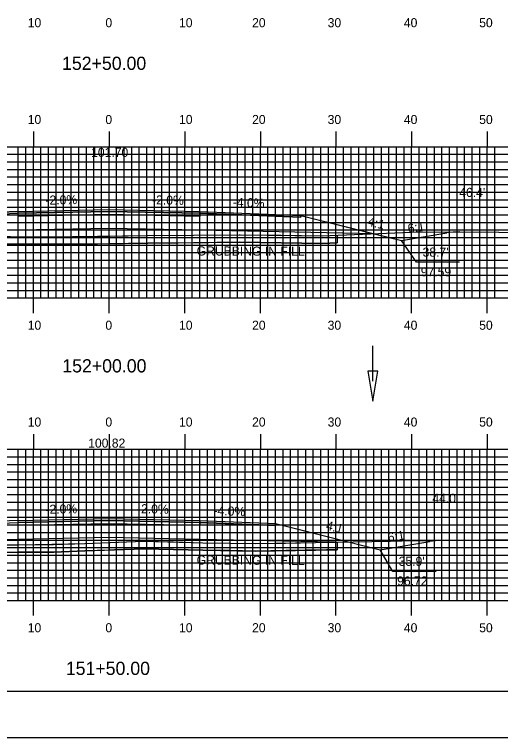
# Model space of a CAD drawing. Extents: x 1778712 to 1779055, y 442591 to 442811.
# Drawn here: x 1778865.3 to 1778929.6, y 442590.5 to 442686.2 of the extents above; entities that cross this region are included whole.
import ezdxf

# ---------------------------------------------------------------- set-up
doc = ezdxf.new("R2010")
doc.units = 0
for name, color, linetype in [('ANNOTATION', 7, 'Continuous'), ('BORDER', 7, 'Continuous'), ('D_Drainage_Ditch_Line', 7, 'Continuous'), ('D_Roadway_Centerline', 7, 'Continuous'), ('D_Roadway_Centerline_Text', 7, 'Continuous'), ('D_Roadway_Edge_Shoulder', 7, 'Continuous'), ('D_Roadway_Edge_TW', 7, 'Continuous'), ('D_Roadway_Pavement', 7, 'Continuous'), ('D_Roadway_SlopeLines', 7, 'Continuous'), ('D_Roadway_SubGrade', 7, 'Continuous'), ('D_Text_Standard', 7, 'Continuous'), ('GRUBBING IN FILL', 7, 'Continuous'), ('H_V ANNOTATION', 7, 'Continuous'), ('MAJOR', 7, 'Continuous'), ('MINOR', 7, 'Continuous'), ('PLOT BOUNDARY', 7, 'Continuous'), ('S_Roadway_Centerline', 7, 'Continuous')]:
    doc.layers.add(name, color=color, linetype=linetype)

msp = doc.modelspace()

# ---------------------------------------------------------------- linework, layer by layer
at = {"layer": 'ANNOTATION'}
for points in [[(1778924.146, 442653.401), (1778918.454, 442653.401), (1778916.47, 442656.259)], [(1778921.039, 442612.52), (1778915.347, 442612.52), (1778913.67, 442615.384)]]:
    msp.add_lwpolyline(points, dxfattribs=at)
at = {"layer": 'BORDER'}
msp.add_lwpolyline([(1778728.216, 442596.665), (1779048.216, 442596.665), (1779048.216, 442806.665), (1778728.216, 442806.665)], close=True, dxfattribs=at)
at = {"layer": 'D_Drainage_Ditch_Line'}
msp.add_line((1778912.679, 442637.661), (1778912.678, 442642.36), dxfattribs=at)
msp.add_lwpolyline([(1778913.335, 442638.974), (1778912.022, 442638.974), (1778912.679, 442635.037)], close=True, dxfattribs=at)
at = {"layer": 'D_Roadway_Centerline'}
msp.add_lwpolyline([(1778842.631, 442656.331), (1778842.722, 442656.331), (1778842.883, 442656.331), (1778843.136, 442656.319), (1778843.376, 442656.296), (1778843.389, 442656.295), (1778843.41, 442656.292), (1778843.642, 442656.259), (1778846.32, 442656.929), (1778847.642, 442657.259), (1778857.816, 442659.802), (1778859.485, 442659.869), (1778865.816, 442660.122), (1778877.816, 442660.362), (1778881.804, 442660.282), (1778889.816, 442660.122), (1778903.149, 442659.589), (1778912.858, 442657.162), (1778916.47, 442656.259)], dxfattribs=at)
at = {"layer": 'D_Roadway_Edge_Shoulder'}
for points in [[(1778865.816, 442660.122), (1778857.816, 442659.802), (1778857.816, 442659.552), (1778865.816, 442659.872)], [(1778889.816, 442660.122), (1778903.149, 442659.589), (1778903.149, 442659.339), (1778889.816, 442659.872)], [(1778865.816, 442619.247), (1778857.816, 442618.927), (1778857.816, 442618.677), (1778865.816, 442618.997)], [(1778889.816, 442619.247), (1778899.816, 442618.847), (1778899.816, 442618.597), (1778889.816, 442618.997)]]:
    msp.add_lwpolyline(points, close=True, dxfattribs=at)
at = {"layer": 'D_Roadway_Edge_TW'}
for points in [[(1778865.816, 442659.872), (1778865.816, 442660.122), (1778877.816, 442660.362), (1778889.816, 442660.122), (1778889.816, 442659.872), (1778877.816, 442660.112)], [(1778865.816, 442618.997), (1778865.816, 442619.247), (1778877.816, 442619.487), (1778889.816, 442619.247), (1778889.816, 442618.997), (1778877.816, 442619.237)]]:
    msp.add_lwpolyline(points, close=True, dxfattribs=at)
at = {"layer": 'D_Roadway_Pavement'}
for points in [[(1778865.816, 442659.456), (1778865.816, 442659.872), (1778877.816, 442660.112), (1778889.816, 442659.872), (1778889.816, 442659.456), (1778877.816, 442659.696)], [(1778865.816, 442618.581), (1778865.816, 442618.997), (1778877.816, 442619.237), (1778889.816, 442618.997), (1778889.816, 442618.581), (1778877.816, 442618.821)]]:
    msp.add_lwpolyline(points, close=True, dxfattribs=at)
at = {"layer": 'D_Roadway_SlopeLines'}
for points in [[(1778903.149, 442659.589), (1778916.47, 442656.259)], [(1778916.47, 442656.259), (1778922.458, 442657.258)], [(1778899.816, 442618.847), (1778913.67, 442615.384)], [(1778913.67, 442615.384), (1778920.204, 442616.473)]]:
    msp.add_lwpolyline(points, dxfattribs=at)
for centre, start, end in [((1778924.103, 442647.394), 89.59856, 99.46701), ((1778921.848, 442606.609), 90.80497, 99.46232)]:
    msp.add_arc(centre, 10, start, end, dxfattribs=at)
at = {"layer": 'D_Roadway_SubGrade'}
for points in [[(1778865.816, 442657.622), (1778847.642, 442657.259), (1778857.816, 442659.802), (1778857.816, 442659.552), (1778865.816, 442659.872), (1778877.816, 442660.112), (1778889.816, 442659.872), (1778903.149, 442659.339), (1778903.149, 442659.589), (1778912.858, 442657.162), (1778889.816, 442657.622), (1778877.816, 442657.862)], [(1778865.816, 442616.747), (1778847.642, 442616.384), (1778857.816, 442618.927), (1778857.816, 442618.677), (1778865.816, 442618.997), (1778877.816, 442619.237), (1778889.816, 442618.997), (1778899.816, 442618.597), (1778899.816, 442618.847), (1778909.815, 442616.348), (1778889.816, 442616.747), (1778877.816, 442616.987)]]:
    msp.add_lwpolyline(points, close=True, dxfattribs=at)
at = {"layer": 'GRUBBING IN FILL'}
for p, q in [((1778907.99, 442656.971), (1778907.99, 442655.97)), ((1778907.99, 442656.971), (1778907.99, 442655.97)), ((1778907.99, 442616.371), (1778907.99, 442615.371)), ((1778907.99, 442616.371), (1778907.99, 442615.371))]:
    msp.add_line(p, q, dxfattribs=at)
for points in [[(1778847.642, 442656.456), (1778848.306, 442656.475), (1778850.185, 442656.529), (1778854.875, 442656.682), (1778859.566, 442656.834), (1778864.784, 442656.8), (1778870.002, 442656.765), (1778872.983, 442656.777), (1778877.816, 442656.845), (1778877.816, 442655.845), (1778872.992, 442655.777), (1778870.001, 442655.765), (1778864.79, 442655.8), (1778859.579, 442655.834), (1778854.897, 442655.682), (1778847.642, 442655.456)], [(1778847.642, 442656.456), (1778848.306, 442656.475), (1778850.185, 442656.529), (1778854.875, 442656.682), (1778859.566, 442656.834), (1778864.784, 442656.8), (1778870.002, 442656.765), (1778872.983, 442656.777), (1778877.816, 442656.845), (1778877.816, 442655.845), (1778872.992, 442655.777), (1778870.001, 442655.765), (1778864.79, 442655.8), (1778859.579, 442655.834), (1778854.897, 442655.682), (1778847.642, 442655.456)], [(1778877.816, 442656.845), (1778882.913, 442656.917), (1778888.971, 442656.977), (1778895.158, 442657.035), (1778900.582, 442656.96), (1778906.006, 442656.886), (1778907.99, 442656.971), (1778907.99, 442655.97), (1778907.005, 442655.928), (1778906.02, 442655.886), (1778900.583, 442655.96), (1778895.114, 442656.035), (1778888.976, 442655.977), (1778882.925, 442655.917), (1778877.816, 442655.845)], [(1778877.816, 442656.845), (1778882.913, 442656.917), (1778888.971, 442656.977), (1778895.158, 442657.035), (1778900.582, 442656.96), (1778906.006, 442656.886), (1778907.99, 442656.971), (1778907.99, 442655.97), (1778907.005, 442655.928), (1778906.02, 442655.886), (1778900.583, 442655.96), (1778895.114, 442656.035), (1778888.976, 442655.977), (1778882.925, 442655.917), (1778877.816, 442655.845)], [(1778847.642, 442614.901), (1778847.642, 442615.902), (1778851.685, 442616.011), (1778854.763, 442616.015), (1778861.781, 442616.033), (1778868.104, 442616.05), (1778874.6, 442616.221), (1778877.816, 442616.334), (1778877.816, 442615.333), (1778874.638, 442615.222), (1778870.508, 442615.053), (1778865.724, 442615.048), (1778857.843, 442615.018), (1778851.699, 442615.011)], [(1778847.642, 442614.901), (1778847.642, 442615.902), (1778851.685, 442616.011), (1778854.763, 442616.015), (1778861.781, 442616.033), (1778868.104, 442616.05), (1778874.6, 442616.221), (1778877.816, 442616.334), (1778877.816, 442615.333), (1778874.638, 442615.222), (1778870.508, 442615.053), (1778865.724, 442615.048), (1778857.843, 442615.018), (1778851.699, 442615.011)], [(1778877.816, 442616.334), (1778882.435, 442616.495), (1778886.333, 442616.403), (1778890.23, 442616.31), (1778893.722, 442616.26), (1778897.213, 442616.21), (1778901.162, 442616.266), (1778905.11, 442616.322), (1778907.99, 442616.371), (1778907.99, 442615.371), (1778906.558, 442615.347), (1778901.169, 442615.266), (1778897.213, 442615.21), (1778893.712, 442615.26), (1778890.211, 442615.311), (1778886.326, 442615.403), (1778882.441, 442615.495), (1778878.539, 442615.358), (1778877.816, 442615.333)], [(1778877.816, 442616.334), (1778882.435, 442616.495), (1778886.333, 442616.403), (1778890.23, 442616.31), (1778893.722, 442616.26), (1778897.213, 442616.21), (1778901.162, 442616.266), (1778905.11, 442616.322), (1778907.99, 442616.371), (1778907.99, 442615.371), (1778906.558, 442615.347), (1778901.169, 442615.266), (1778897.213, 442615.21), (1778893.712, 442615.26), (1778890.211, 442615.311), (1778886.326, 442615.403), (1778882.441, 442615.495), (1778878.539, 442615.358), (1778877.816, 442615.333)]]:
    msp.add_lwpolyline(points, close=True, dxfattribs=at)
for points in [[(1778847.642, 442655.456), (1778850.215, 442655.53), (1778859.579, 442655.834), (1778870.001, 442655.765), (1778872.992, 442655.777), (1778882.925, 442655.917), (1778895.028, 442656.037), (1778895.082, 442656.036), (1778895.146, 442656.035), (1778906.02, 442655.886), (1778907.99, 442655.97)], [(1778847.642, 442655.456), (1778850.215, 442655.53), (1778859.579, 442655.834), (1778870.001, 442655.765), (1778872.992, 442655.777), (1778882.925, 442655.917), (1778895.028, 442656.037), (1778895.082, 442656.036), (1778895.146, 442656.035), (1778906.02, 442655.886), (1778907.99, 442655.97)], [(1778847.642, 442614.901), (1778851.699, 442615.011), (1778857.843, 442615.018), (1778865.724, 442615.048), (1778870.508, 442615.053), (1778874.638, 442615.222), (1778882.441, 442615.495), (1778890.211, 442615.311), (1778897.213, 442615.21), (1778905.126, 442615.323), (1778907.99, 442615.371)], [(1778847.642, 442614.901), (1778851.699, 442615.011), (1778857.843, 442615.018), (1778865.724, 442615.048), (1778870.508, 442615.053), (1778874.638, 442615.222), (1778882.441, 442615.495), (1778890.211, 442615.311), (1778897.213, 442615.21), (1778905.126, 442615.323), (1778907.99, 442615.371)]]:
    msp.add_lwpolyline(points, dxfattribs=at)
at = {"layer": 'MAJOR'}
for p, q in [((1778867.816, 442670.669), (1778867.816, 442668.665)), ((1778877.816, 442670.669), (1778877.816, 442668.665)), ((1778887.816, 442670.669), (1778887.816, 442668.665)), ((1778897.816, 442670.669), (1778897.816, 442668.665)), ((1778907.816, 442670.669), (1778907.816, 442668.665)), ((1778917.816, 442670.669), (1778917.816, 442668.665)), ((1778927.816, 442670.669), (1778927.816, 442668.665)), ((1778737.816, 442668.665), (1779017.816, 442668.665)), ((1778737.816, 442668.665), (1779017.816, 442668.665)), ((1778867.816, 442648.665), (1778867.816, 442668.665)), ((1778877.816, 442648.665), (1778877.816, 442668.665)), ((1778887.816, 442648.665), (1778887.816, 442668.665)), ((1778897.816, 442648.665), (1778897.816, 442668.665)), ((1778907.816, 442648.665), (1778907.816, 442668.665)), ((1778917.816, 442648.665), (1778917.816, 442668.665)), ((1778927.816, 442648.665), (1778927.816, 442668.665)), ((1778737.816, 442663.665), (1779017.816, 442663.665)), ((1778737.816, 442658.665), (1779017.816, 442658.665)), ((1778737.816, 442653.665), (1779017.816, 442653.665)), ((1778737.816, 442648.665), (1779017.816, 442648.665)), ((1778737.816, 442648.665), (1779017.816, 442648.665)), ((1778867.816, 442646.661), (1778867.816, 442648.665)), ((1778877.816, 442646.661), (1778877.816, 442648.665)), ((1778887.816, 442646.661), (1778887.816, 442648.665)), ((1778897.816, 442646.661), (1778897.816, 442648.665)), ((1778907.816, 442646.661), (1778907.816, 442648.665)), ((1778917.816, 442646.661), (1778917.816, 442648.665)), ((1778927.816, 442646.661), (1778927.816, 442648.665)), ((1778867.816, 442630.669), (1778867.816, 442628.665)), ((1778877.816, 442630.669), (1778877.816, 442628.665)), ((1778887.816, 442630.669), (1778887.816, 442628.665)), ((1778897.816, 442630.669), (1778897.816, 442628.665)), ((1778907.816, 442630.669), (1778907.816, 442628.665)), ((1778917.816, 442630.669), (1778917.816, 442628.665)), ((1778927.816, 442630.669), (1778927.816, 442628.665)), ((1778737.816, 442628.665), (1779017.816, 442628.665)), ((1778737.816, 442628.665), (1779017.816, 442628.665)), ((1778867.816, 442608.665), (1778867.816, 442628.665)), ((1778877.816, 442608.665), (1778877.816, 442628.665)), ((1778887.816, 442608.665), (1778887.816, 442628.665)), ((1778897.816, 442608.665), (1778897.816, 442628.665)), ((1778907.816, 442608.665), (1778907.816, 442628.665)), ((1778917.816, 442608.665), (1778917.816, 442628.665)), ((1778927.816, 442608.665), (1778927.816, 442628.665)), ((1778737.816, 442623.665), (1779017.816, 442623.665)), ((1778737.816, 442618.665), (1779017.816, 442618.665)), ((1778737.816, 442613.665), (1779017.816, 442613.665)), ((1778737.816, 442608.665), (1779017.816, 442608.665)), ((1778737.816, 442608.665), (1779017.816, 442608.665)), ((1778867.816, 442606.661), (1778867.816, 442608.665)), ((1778877.816, 442606.661), (1778877.816, 442608.665)), ((1778887.816, 442606.661), (1778887.816, 442608.665)), ((1778897.816, 442606.661), (1778897.816, 442608.665)), ((1778907.816, 442606.661), (1778907.816, 442608.665)), ((1778917.816, 442606.661), (1778917.816, 442608.665)), ((1778927.816, 442606.661), (1778927.816, 442608.665))]:
    msp.add_line(p, q, dxfattribs=at)
at = {"layer": 'MINOR'}
for p, q in [((1778865.816, 442648.665), (1778865.816, 442668.665)), ((1778866.816, 442648.665), (1778866.816, 442668.665)), ((1778868.816, 442648.665), (1778868.816, 442668.665)), ((1778869.816, 442648.665), (1778869.816, 442668.665)), ((1778870.816, 442648.665), (1778870.816, 442668.665)), ((1778871.816, 442648.665), (1778871.816, 442668.665)), ((1778872.816, 442648.665), (1778872.816, 442668.665)), ((1778873.816, 442648.665), (1778873.816, 442668.665)), ((1778874.816, 442648.665), (1778874.816, 442668.665)), ((1778875.816, 442648.665), (1778875.816, 442668.665)), ((1778876.816, 442648.665), (1778876.816, 442668.665)), ((1778878.816, 442648.665), (1778878.816, 442668.665)), ((1778879.816, 442648.665), (1778879.816, 442668.665)), ((1778880.816, 442648.665), (1778880.816, 442668.665)), ((1778881.816, 442648.665), (1778881.816, 442668.665)), ((1778882.816, 442648.665), (1778882.816, 442668.665)), ((1778883.816, 442648.665), (1778883.816, 442668.665)), ((1778884.816, 442648.665), (1778884.816, 442668.665)), ((1778885.816, 442648.665), (1778885.816, 442668.665)), ((1778886.816, 442648.665), (1778886.816, 442668.665)), ((1778888.816, 442648.665), (1778888.816, 442668.665)), ((1778889.816, 442648.665), (1778889.816, 442668.665)), ((1778890.816, 442648.665), (1778890.816, 442668.665)), ((1778891.816, 442648.665), (1778891.816, 442668.665)), ((1778892.816, 442648.665), (1778892.816, 442668.665)), ((1778893.816, 442648.665), (1778893.816, 442668.665)), ((1778894.816, 442648.665), (1778894.816, 442668.665)), ((1778895.816, 442648.665), (1778895.816, 442668.665)), ((1778896.816, 442648.665), (1778896.816, 442668.665)), ((1778898.816, 442648.665), (1778898.816, 442668.665)), ((1778899.816, 442648.665), (1778899.816, 442668.665)), ((1778900.816, 442648.665), (1778900.816, 442668.665)), ((1778901.816, 442648.665), (1778901.816, 442668.665)), ((1778902.816, 442648.665), (1778902.816, 442668.665)), ((1778903.816, 442648.665), (1778903.816, 442668.665)), ((1778904.816, 442648.665), (1778904.816, 442668.665)), ((1778905.816, 442648.665), (1778905.816, 442668.665)), ((1778906.816, 442648.665), (1778906.816, 442668.665)), ((1778908.816, 442648.665), (1778908.816, 442668.665)), ((1778909.816, 442648.665), (1778909.816, 442668.665)), ((1778910.816, 442648.665), (1778910.816, 442668.665)), ((1778911.816, 442648.665), (1778911.816, 442668.665)), ((1778912.816, 442648.665), (1778912.816, 442668.665)), ((1778913.816, 442648.665), (1778913.816, 442668.665)), ((1778914.816, 442648.665), (1778914.816, 442668.665)), ((1778915.816, 442648.665), (1778915.816, 442668.665)), ((1778916.816, 442648.665), (1778916.816, 442668.665)), ((1778918.816, 442648.665), (1778918.816, 442668.665)), ((1778919.816, 442648.665), (1778919.816, 442668.665)), ((1778920.816, 442648.665), (1778920.816, 442668.665)), ((1778921.816, 442648.665), (1778921.816, 442668.665)), ((1778922.816, 442648.665), (1778922.816, 442668.665)), ((1778923.816, 442648.665), (1778923.816, 442668.665)), ((1778924.816, 442648.665), (1778924.816, 442668.665)), ((1778925.816, 442648.665), (1778925.816, 442668.665)), ((1778926.816, 442648.665), (1778926.816, 442668.665)), ((1778928.816, 442648.665), (1778928.816, 442668.665)), ((1778737.816, 442667.665), (1779017.816, 442667.665)), ((1778737.816, 442666.665), (1779017.816, 442666.665)), ((1778737.816, 442665.665), (1779017.816, 442665.665)), ((1778737.816, 442664.665), (1779017.816, 442664.665)), ((1778737.816, 442662.665), (1779017.816, 442662.665)), ((1778737.816, 442661.665), (1779017.816, 442661.665)), ((1778737.816, 442660.665), (1779017.816, 442660.665)), ((1778737.816, 442659.665), (1779017.816, 442659.665)), ((1778737.816, 442657.665), (1779017.816, 442657.665)), ((1778737.816, 442656.665), (1779017.816, 442656.665)), ((1778737.816, 442655.665), (1779017.816, 442655.665)), ((1778737.816, 442654.665), (1779017.816, 442654.665)), ((1778737.816, 442652.665), (1779017.816, 442652.665)), ((1778737.816, 442651.665), (1779017.816, 442651.665)), ((1778737.816, 442650.665), (1779017.816, 442650.665)), ((1778737.816, 442649.665), (1779017.816, 442649.665)), ((1778865.816, 442608.665), (1778865.816, 442628.665)), ((1778866.816, 442608.665), (1778866.816, 442628.665)), ((1778868.816, 442608.665), (1778868.816, 442628.665)), ((1778869.816, 442608.665), (1778869.816, 442628.665)), ((1778870.816, 442608.665), (1778870.816, 442628.665)), ((1778871.816, 442608.665), (1778871.816, 442628.665)), ((1778872.816, 442608.665), (1778872.816, 442628.665)), ((1778873.816, 442608.665), (1778873.816, 442628.665)), ((1778874.816, 442608.665), (1778874.816, 442628.665)), ((1778875.816, 442608.665), (1778875.816, 442628.665)), ((1778876.816, 442608.665), (1778876.816, 442628.665)), ((1778878.816, 442608.665), (1778878.816, 442628.665)), ((1778879.816, 442608.665), (1778879.816, 442628.665)), ((1778880.816, 442608.665), (1778880.816, 442628.665)), ((1778881.816, 442608.665), (1778881.816, 442628.665)), ((1778882.816, 442608.665), (1778882.816, 442628.665)), ((1778883.816, 442608.665), (1778883.816, 442628.665)), ((1778884.816, 442608.665), (1778884.816, 442628.665)), ((1778885.816, 442608.665), (1778885.816, 442628.665)), ((1778886.816, 442608.665), (1778886.816, 442628.665)), ((1778888.816, 442608.665), (1778888.816, 442628.665)), ((1778889.816, 442608.665), (1778889.816, 442628.665)), ((1778890.816, 442608.665), (1778890.816, 442628.665)), ((1778891.816, 442608.665), (1778891.816, 442628.665)), ((1778892.816, 442608.665), (1778892.816, 442628.665)), ((1778893.816, 442608.665), (1778893.816, 442628.665)), ((1778894.816, 442608.665), (1778894.816, 442628.665)), ((1778895.816, 442608.665), (1778895.816, 442628.665)), ((1778896.816, 442608.665), (1778896.816, 442628.665)), ((1778898.816, 442608.665), (1778898.816, 442628.665)), ((1778899.816, 442608.665), (1778899.816, 442628.665)), ((1778900.816, 442608.665), (1778900.816, 442628.665)), ((1778901.816, 442608.665), (1778901.816, 442628.665)), ((1778902.816, 442608.665), (1778902.816, 442628.665)), ((1778903.816, 442608.665), (1778903.816, 442628.665)), ((1778904.816, 442608.665), (1778904.816, 442628.665)), ((1778905.816, 442608.665), (1778905.816, 442628.665)), ((1778906.816, 442608.665), (1778906.816, 442628.665)), ((1778908.816, 442608.665), (1778908.816, 442628.665)), ((1778909.816, 442608.665), (1778909.816, 442628.665)), ((1778910.816, 442608.665), (1778910.816, 442628.665)), ((1778911.816, 442608.665), (1778911.816, 442628.665)), ((1778912.816, 442608.665), (1778912.816, 442628.665)), ((1778913.816, 442608.665), (1778913.816, 442628.665)), ((1778914.816, 442608.665), (1778914.816, 442628.665)), ((1778915.816, 442608.665), (1778915.816, 442628.665)), ((1778916.816, 442608.665), (1778916.816, 442628.665)), ((1778918.816, 442608.665), (1778918.816, 442628.665)), ((1778919.816, 442608.665), (1778919.816, 442628.665)), ((1778920.816, 442608.665), (1778920.816, 442628.665)), ((1778921.816, 442608.665), (1778921.816, 442628.665)), ((1778922.816, 442608.665), (1778922.816, 442628.665)), ((1778923.816, 442608.665), (1778923.816, 442628.665)), ((1778924.816, 442608.665), (1778924.816, 442628.665)), ((1778925.816, 442608.665), (1778925.816, 442628.665)), ((1778926.816, 442608.665), (1778926.816, 442628.665)), ((1778928.816, 442608.665), (1778928.816, 442628.665)), ((1778737.816, 442627.665), (1779017.816, 442627.665)), ((1778737.816, 442626.665), (1779017.816, 442626.665)), ((1778737.816, 442625.665), (1779017.816, 442625.665)), ((1778737.816, 442624.665), (1779017.816, 442624.665)), ((1778737.816, 442622.665), (1779017.816, 442622.665)), ((1778737.816, 442621.665), (1779017.816, 442621.665)), ((1778737.816, 442620.665), (1779017.816, 442620.665)), ((1778737.816, 442619.665), (1779017.816, 442619.665)), ((1778737.816, 442617.665), (1779017.816, 442617.665)), ((1778737.816, 442616.665), (1779017.816, 442616.665)), ((1778737.816, 442615.665), (1779017.816, 442615.665)), ((1778737.816, 442614.665), (1779017.816, 442614.665)), ((1778737.816, 442612.665), (1779017.816, 442612.665)), ((1778737.816, 442611.665), (1779017.816, 442611.665)), ((1778737.816, 442610.665), (1779017.816, 442610.665)), ((1778737.816, 442609.665), (1779017.816, 442609.665))]:
    msp.add_line(p, q, dxfattribs=at)
at = {"layer": 'PLOT BOUNDARY'}
msp.add_lwpolyline([(1778712.029, 442590.547), (1779052.029, 442590.547), (1779052.029, 442810.547), (1778712.029, 442810.547)], close=True, dxfattribs=at)
at = {"layer": 'S_Roadway_Centerline'}
for points in [[(1778813.946, 442656.402), (1778826.915, 442656.052), (1778836.598, 442656.188), (1778846.427, 442656.422), (1778850.185, 442656.529), (1778859.566, 442656.834), (1778870.002, 442656.765), (1778872.983, 442656.777), (1778882.913, 442656.917), (1778895.029, 442657.037), (1778895.093, 442657.036), (1778895.158, 442657.035), (1778906.006, 442656.886), (1778917.727, 442657.387), (1778918.527, 442657.421), (1778919.257, 442657.428), (1778929.36, 442657.357), (1778940.033, 442657.27)], [(1778817.437, 442615.533), (1778827.835, 442615.539), (1778835.333, 442615.477), (1778842.558, 442615.764), (1778851.685, 442616.011), (1778857.84, 442616.018), (1778865.721, 442616.048), (1778870.487, 442616.053), (1778874.6, 442616.221), (1778882.435, 442616.495), (1778890.23, 442616.31), (1778897.213, 442616.21), (1778905.11, 442616.322), (1778915.021, 442616.491), (1778918.005, 442616.612), (1778920.68, 442616.594), (1778937.869, 442616.835)]]:
    msp.add_lwpolyline(points, dxfattribs=at)

# ---------------------------------------------------------------- texts
at = {"layer": 'ANNOTATION'}
for s, rotation, p in [('-2.0%', 1.14576, (1778869.422, 442660.995)), ('-2.0%', 358.85424, (1778883.496, 442661.049)), ('-4.0%', 357.70947, (1778894.154, 442660.75)), ('4:1', 345.96489, (1778911.912, 442658.26)), ('6:1', 9.46702, (1778917.394, 442657.241)), ('-2.0%', 1.14576, (1778869.422, 442620.12)), ('-2.0%', 358.85419, (1778881.503, 442620.214)), ('-4.0%', 357.70947, (1778891.608, 442619.977)), ('4:1', 345.96527, (1778906.409, 442618.061)), ('6:1', 9.45866, (1778914.753, 442616.392))]:
    msp.add_text(s, height=1.2, rotation=rotation, dxfattribs=at).set_placement(p)
for s, p in [("38.7'", (1778919.263, 442654.127)), ('97.59', (1778919.022, 442651.527)), ("35.9'", (1778916.103, 442613.246)), ('96.72', (1778915.899, 442610.646))]:
    msp.add_text(s, height=1.2, dxfattribs=at).set_placement(p)
at = {"layer": 'D_Roadway_Centerline'}
for s, p in [('C', (1778877.811, 442660.362)), ('L', (1778877.816, 442660.355)), ('C', (1778877.811, 442619.487)), ('L', (1778877.816, 442619.48))]:
    msp.add_text(s, height=0.0146, dxfattribs=at).set_placement(p)
at = {"layer": 'D_Roadway_Centerline_Text'}
for s, p in [('101.70', (1778875.451, 442667.32)), ('100.82', (1778875.06, 442628.877))]:
    msp.add_text(s, height=1.2, dxfattribs=at).set_placement(p)
at = {"layer": 'D_Text_Standard'}
for s, p in [("46.4'", (1778924.105, 442662.026)), ("44.0'", (1778920.547, 442621.58))]:
    msp.add_text(s, height=1.2, dxfattribs=at).set_placement(p)
at = {"layer": 'GRUBBING IN FILL'}
for p in [(1778889.399, 442654.289), (1778889.399, 442613.421)]:
    msp.add_text('GRUBBING IN FILL', height=1.2, rotation=359.80532, dxfattribs=at).set_placement(p)
at = {"layer": 'H_V ANNOTATION'}
for s, height, p in [('10', 1.2, (1778867.067, 442684.465)), ('0', 1.2, (1778877.334, 442684.465)), ('10', 1.2, (1778887.067, 442684.465)), ('20', 1.2, (1778896.724, 442684.465)), ('30', 1.2, (1778906.713, 442684.465)), ('40', 1.2, (1778916.788, 442684.465)), ('50', 1.2, (1778926.745, 442684.465)), ('152+50.00', 1.75, (1778871.605, 442678.821)), ('10', 1.2, (1778867.067, 442671.665)), ('0', 1.2, (1778877.334, 442671.665)), ('10', 1.2, (1778887.067, 442671.665)), ('20', 1.2, (1778896.724, 442671.665)), ('30', 1.2, (1778906.713, 442671.665)), ('40', 1.2, (1778916.788, 442671.665)), ('50', 1.2, (1778926.745, 442671.665)), ('10', 1.2, (1778867.067, 442644.465)), ('0', 1.2, (1778877.334, 442644.465)), ('10', 1.2, (1778887.067, 442644.465)), ('20', 1.2, (1778896.724, 442644.465)), ('30', 1.2, (1778906.713, 442644.465)), ('40', 1.2, (1778916.788, 442644.465)), ('50', 1.2, (1778926.745, 442644.465)), ('152+00.00', 1.75, (1778871.636, 442638.821)), ('10', 1.2, (1778867.067, 442631.665)), ('0', 1.2, (1778877.334, 442631.665)), ('10', 1.2, (1778887.067, 442631.665)), ('20', 1.2, (1778896.724, 442631.665)), ('30', 1.2, (1778906.713, 442631.665)), ('40', 1.2, (1778916.788, 442631.665)), ('50', 1.2, (1778926.745, 442631.665)), ('10', 1.2, (1778867.067, 442604.465)), ('0', 1.2, (1778877.334, 442604.465)), ('10', 1.2, (1778887.067, 442604.465)), ('20', 1.2, (1778896.724, 442604.465)), ('30', 1.2, (1778906.713, 442604.465)), ('40', 1.2, (1778916.788, 442604.465)), ('50', 1.2, (1778926.745, 442604.465)), ('151+50.00', 1.75, (1778872.104, 442598.821))]:
    msp.add_text(s, height=height, dxfattribs=at).set_placement(p)

doc.saveas('drawing.dxf')
